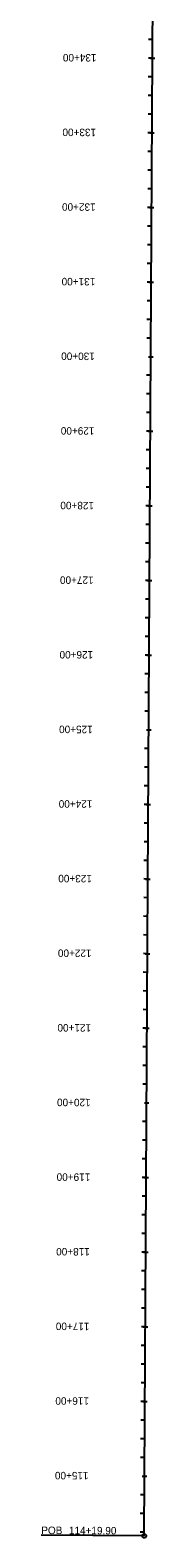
# Model space of a CAD drawing. Extents: x 23417911 to 23421158, y 6737892 to 6791804.
# Drawn here: x 23418127 to 23418279, y 6737892 to 6739912 of the extents above; entities that cross this region are included whole.
import ezdxf

# ---------------------------------------------------------------- set-up
doc = ezdxf.new("R2010")
doc.units = 0
for name, color, linetype in [('Alignment', 7, 'Continuous'), ('TextAlignment', 7, 'Continuous'), ('TextAlignmentLrg', 7, 'Continuous'), ('TextAlignmentSml', 7, 'Continuous')]:
    doc.layers.add(name, color=color, linetype=linetype)

msp = doc.modelspace()

# ---------------------------------------------------------------- linework, layer by layer
at = {"layer": 'Alignment'}
msp.add_line((23418264.8, 6737894.7), (23418277.8, 6740231.7), dxfattribs=at)
at = {"layer": 'TextAlignment'}
for p in [(23418264.8, 6737894.7), (23418126.8, 6737895.5)]:
    msp.add_line(p, (23418126.8, 6737895.5), dxfattribs=at)
msp.add_circle((23418264.8, 6737894.7), 2.67, dxfattribs=at)
at = {"layer": 'TextAlignmentLrg'}
for p, q in [((23418275.8, 6739874.8), (23418270.4, 6739874.8)), ((23418275.3, 6739774.8), (23418269.8, 6739774.8)), ((23418274.7, 6739674.8), (23418269.3, 6739674.8)), ((23418274.2, 6739574.8), (23418268.7, 6739574.8)), ((23418270.5, 6739474.8), (23418276.7, 6739474.8)), ((23418273, 6739374.8), (23418267.6, 6739374.8)), ((23418272.5, 6739274.8), (23418267, 6739274.8)), ((23418271.9, 6739174.8), (23418266.5, 6739174.8)), ((23418271.4, 6739074.8), (23418265.9, 6739074.8)), ((23418267.7, 6738974.8), (23418273.9, 6738974.8)), ((23418270.2, 6738874.8), (23418264.8, 6738874.9)), ((23418269.7, 6738774.8), (23418264.2, 6738774.9)), ((23418269.1, 6738674.8), (23418263.7, 6738674.9)), ((23418268.6, 6738574.8), (23418263.1, 6738574.9)), ((23418265, 6738474.8), (23418271.1, 6738474.8)), ((23418267.5, 6738374.8), (23418262, 6738374.9)), ((23418266.9, 6738274.8), (23418261.4, 6738274.9)), ((23418266.3, 6738174.8), (23418260.9, 6738174.9)), ((23418265.8, 6738074.8), (23418260.3, 6738074.9)), ((23418262.2, 6737974.9), (23418268.3, 6737974.8))]:
    msp.add_line(p, q, dxfattribs=at)
at = {"layer": 'TextAlignmentSml'}
for p, q in [((23418276, 6739899.8), (23418270.5, 6739899.8)), ((23418272.8, 6739874.8), (23418278.9, 6739874.8)), ((23418275.7, 6739849.8), (23418270.2, 6739849.8)), ((23418275.6, 6739824.8), (23418270.1, 6739824.8)), ((23418275.4, 6739799.8), (23418270, 6739799.8)), ((23418272.2, 6739774.8), (23418278.3, 6739774.8)), ((23418275.1, 6739749.8), (23418269.7, 6739749.8)), ((23418275, 6739724.8), (23418269.5, 6739724.8)), ((23418274.9, 6739699.8), (23418269.4, 6739699.8)), ((23418271.7, 6739674.8), (23418277.8, 6739674.8)), ((23418274.6, 6739649.8), (23418269.1, 6739649.8)), ((23418274.4, 6739624.8), (23418269, 6739624.8)), ((23418274.3, 6739599.8), (23418268.8, 6739599.8)), ((23418271.1, 6739574.8), (23418277.2, 6739574.8)), ((23418274, 6739549.8), (23418268.6, 6739549.8)), ((23418273.9, 6739524.8), (23418268.4, 6739524.8)), ((23418273.7, 6739499.8), (23418268.3, 6739499.8)), ((23418270.5, 6739474.8), (23418276.7, 6739474.8)), ((23418273.5, 6739449.8), (23418268, 6739449.8)), ((23418273.3, 6739424.8), (23418267.9, 6739424.8)), ((23418273.2, 6739399.8), (23418267.7, 6739399.8)), ((23418270, 6739374.8), (23418276.1, 6739374.8)), ((23418272.9, 6739349.8), (23418267.4, 6739349.8)), ((23418272.8, 6739324.8), (23418267.3, 6739324.8)), ((23418272.6, 6739299.8), (23418267.2, 6739299.8)), ((23418269.4, 6739274.8), (23418275.5, 6739274.8)), ((23418272.3, 6739249.8), (23418266.9, 6739249.8)), ((23418272.2, 6739224.8), (23418266.7, 6739224.8)), ((23418272.1, 6739199.8), (23418266.6, 6739199.8)), ((23418268.9, 6739174.8), (23418275, 6739174.8)), ((23418271.8, 6739149.8), (23418266.3, 6739149.8)), ((23418271.6, 6739124.8), (23418266.2, 6739124.8)), ((23418271.5, 6739099.8), (23418266, 6739099.8)), ((23418268.3, 6739074.8), (23418274.4, 6739074.8)), ((23418271.2, 6739049.8), (23418265.8, 6739049.8)), ((23418271.1, 6739024.8), (23418265.6, 6739024.8)), ((23418270.9, 6738999.8), (23418265.5, 6738999.8)), ((23418267.7, 6738974.8), (23418273.9, 6738974.8)), ((23418270.7, 6738949.8), (23418265.2, 6738949.9)), ((23418270.5, 6738924.8), (23418265.1, 6738924.9)), ((23418270.4, 6738899.8), (23418264.9, 6738899.9)), ((23418267.2, 6738874.8), (23418273.3, 6738874.8)), ((23418270.1, 6738849.8), (23418264.6, 6738849.9)), ((23418270, 6738824.8), (23418264.5, 6738824.9)), ((23418269.8, 6738799.8), (23418264.4, 6738799.9)), ((23418266.6, 6738774.8), (23418272.7, 6738774.8)), ((23418269.5, 6738749.8), (23418264.1, 6738749.9)), ((23418269.4, 6738724.8), (23418263.9, 6738724.9)), ((23418269.3, 6738699.8), (23418263.8, 6738699.9)), ((23418266.1, 6738674.8), (23418272.2, 6738674.8)), ((23418269, 6738649.8), (23418263.5, 6738649.9)), ((23418268.8, 6738624.8), (23418263.4, 6738624.9)), ((23418268.7, 6738599.8), (23418263.2, 6738599.9)), ((23418265.5, 6738574.8), (23418271.6, 6738574.8)), ((23418268.4, 6738549.8), (23418263, 6738549.9)), ((23418268.3, 6738524.8), (23418262.8, 6738524.9)), ((23418268.2, 6738499.8), (23418262.7, 6738499.9)), ((23418265, 6738474.8), (23418271.1, 6738474.8)), ((23418267.9, 6738449.8), (23418262.4, 6738449.9)), ((23418267.7, 6738424.8), (23418262.3, 6738424.9)), ((23418267.6, 6738399.8), (23418262.1, 6738399.9)), ((23418264.4, 6738374.8), (23418270.5, 6738374.8)), ((23418267.3, 6738349.8), (23418261.9, 6738349.9)), ((23418267.2, 6738324.8), (23418261.7, 6738324.9)), ((23418267, 6738299.8), (23418261.6, 6738299.9)), ((23418263.8, 6738274.8), (23418270, 6738274.8)), ((23418266.8, 6738249.8), (23418261.3, 6738249.9)), ((23418266.6, 6738224.8), (23418261.2, 6738224.9)), ((23418266.5, 6738199.8), (23418261, 6738199.9)), ((23418263.3, 6738174.8), (23418269.4, 6738174.8)), ((23418266.2, 6738149.8), (23418260.7, 6738149.9)), ((23418266.1, 6738124.8), (23418260.6, 6738124.9)), ((23418265.9, 6738099.8), (23418260.5, 6738099.9)), ((23418262.7, 6738074.9), (23418268.8, 6738074.8)), ((23418265.6, 6738049.8), (23418260.2, 6738049.9)), ((23418265.5, 6738024.8), (23418260, 6738024.9)), ((23418265.4, 6737999.8), (23418259.9, 6737999.9)), ((23418262.2, 6737974.9), (23418268.3, 6737974.8)), ((23418265.1, 6737949.8), (23418259.6, 6737949.9)), ((23418264.9, 6737924.8), (23418259.5, 6737924.9)), ((23418264.8, 6737899.8), (23418259.3, 6737899.9))]:
    msp.add_line(p, q, dxfattribs=at)

# ---------------------------------------------------------------- texts
at = {"layer": 'TextAlignment'}
for s, p in [('POB ', (23418126.8, 6737897.2)), ('114+19.90', (23418163.8, 6737897))]:
    msp.add_text(s, height=10.02, rotation=359.6799, dxfattribs=at).set_placement(p)
at = {"layer": 'TextAlignmentLrg'}
for s, p in [('130+00', (23418198.6, 6739480.2)), ('125+00', (23418195.8, 6738980.2)), ('120+00', (23418193, 6738480.3)), ('115+00', (23418190.2, 6737980.3))]:
    msp.add_text(s, height=10.02, rotation=179.6799, dxfattribs=at).set_placement(p)
at = {"layer": 'TextAlignmentSml'}
for s, p in [('134+00', (23418200.9, 6739880.2)), ('133+00', (23418200.3, 6739780.2)), ('132+00', (23418199.7, 6739680.2)), ('131+00', (23418199.2, 6739580.2)), ('130+00', (23418198.6, 6739480.2)), ('129+00', (23418198.1, 6739380.2)), ('128+00', (23418197.5, 6739280.2)), ('127+00', (23418197, 6739180.2)), ('126+00', (23418196.4, 6739080.2)), ('125+00', (23418195.8, 6738980.2)), ('124+00', (23418195.3, 6738880.3)), ('123+00', (23418194.7, 6738780.3)), ('122+00', (23418194.2, 6738680.3)), ('121+00', (23418193.6, 6738580.3)), ('120+00', (23418193, 6738480.3)), ('119+00', (23418192.5, 6738380.3)), ('118+00', (23418191.9, 6738280.3)), ('117+00', (23418191.4, 6738180.3)), ('116+00', (23418190.8, 6738080.3)), ('115+00', (23418190.2, 6737980.3))]:
    msp.add_text(s, height=10.02, rotation=179.6799, dxfattribs=at).set_placement(p)

doc.saveas('drawing.dxf')
